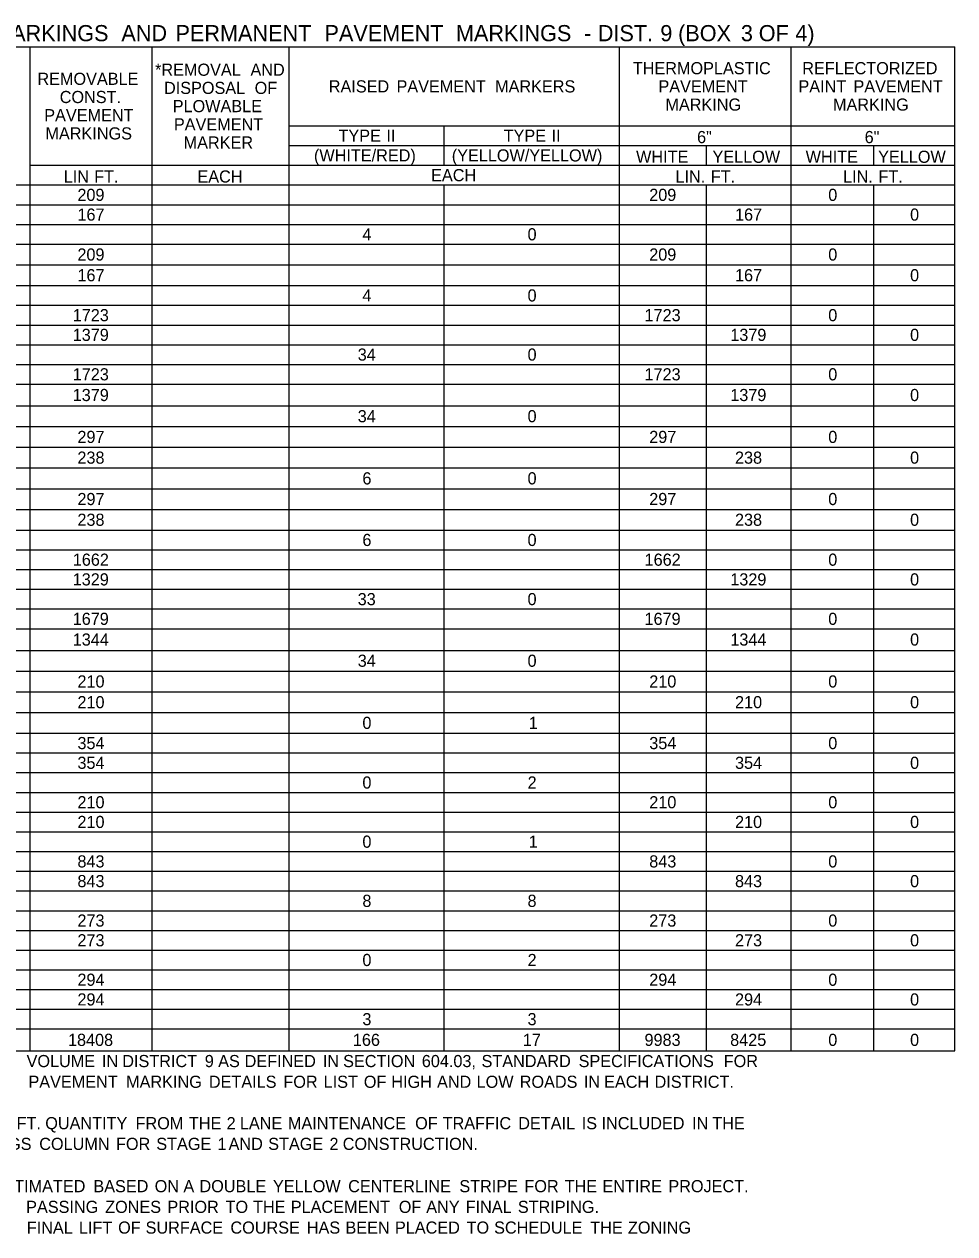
# Model space of a CAD drawing. Extents: x 544420 to 1930787, y -1947044 to 596640.
# Drawn here: x 550212 to 550672, y -1946838 to -1946240 of the extents above; entities that cross this region are included whole.
import ezdxf

# ---------------------------------------------------------------- set-up
doc = ezdxf.new("R2010")
doc.units = 0
doc.layers.add('Default', color=7, linetype='Continuous')

msp = doc.modelspace()

# ---------------------------------------------------------------- linework, layer by layer
at = {"layer": 'Default'}
for p, q in [((549970.43, -1946251.27), (550672.43, -1946251.27)), ((549970.43, -1946251.27), (550275.6, -1946251.27)), ((550215.15, -1946747.55), (550215.15, -1946251.27)), ((550275.6, -1946747.55), (550275.6, -1946251.27)), ((550343.36, -1946747.55), (550343.36, -1946251.27)), ((550506.68, -1946747.55), (550506.68, -1946251.27)), ((550591.5, -1946319.52), (550591.5, -1946251.27)), ((550591.5, -1946747.55), (550591.5, -1946251.27)), ((550672.43, -1946747.55), (550672.43, -1946251.27)), ((550343.36, -1946290.27), (550672.43, -1946290.27)), ((550419.9, -1946309.77), (550419.9, -1946290.27)), ((550343.36, -1946300.02), (550672.43, -1946300.02)), ((550549.58, -1946309.77), (550549.58, -1946300.02)), ((550632.45, -1946309.77), (550632.45, -1946300.02)), ((550215.15, -1946309.77), (550672.43, -1946309.77)), ((550215.15, -1946319.52), (550215.15, -1946309.77)), ((550275.6, -1946319.52), (550275.6, -1946309.77)), ((550343.36, -1946319.52), (550343.36, -1946309.77)), ((550115.7, -1946319.52), (550672.43, -1946319.52)), ((550419.9, -1946747.55), (550419.9, -1946319.52)), ((550506.68, -1946319.52), (550591.5, -1946319.52)), ((550549.58, -1946747.55), (550549.58, -1946319.52)), ((550591.5, -1946319.52), (550672.43, -1946319.52)), ((550632.45, -1946747.55), (550632.45, -1946319.52)), ((550155.19, -1946329.27), (550672.43, -1946329.27)), ((550155.19, -1946339.02), (550672.43, -1946339.02)), ((549970.43, -1946348.77), (550672.43, -1946348.77)), ((550155.19, -1946359.01), (550672.43, -1946359.01)), ((550155.19, -1946369.25), (550672.43, -1946369.25)), ((549970.43, -1946379), (550672.43, -1946379)), ((550155.19, -1946388.75), (550672.43, -1946388.75)), ((550155.19, -1946398.5), (550672.43, -1946398.5)), ((549970.43, -1946408.25), (550672.43, -1946408.25)), ((550155.19, -1946418), (550672.43, -1946418)), ((550155.19, -1946428.72), (550672.43, -1946428.72)), ((549970.43, -1946438.96), (550672.43, -1946438.96)), ((550155.19, -1946449.2), (550672.43, -1946449.2)), ((550155.19, -1946459.44), (550672.43, -1946459.44)), ((549970.43, -1946469.67), (550672.43, -1946469.67)), ((550155.19, -1946479.91), (550672.43, -1946479.91)), ((550155.19, -1946490.15), (550672.43, -1946490.15)), ((549970.43, -1946499.9), (550672.43, -1946499.9)), ((550155.19, -1946509.65), (550672.43, -1946509.65)), ((550155.19, -1946519.4), (550672.43, -1946519.4)), ((549970.43, -1946529.15), (550672.43, -1946529.15)), ((550155.19, -1946538.9), (550672.43, -1946538.9)), ((550155.19, -1946549.62), (550672.43, -1946549.62)), ((549970.43, -1946559.86), (550672.43, -1946559.86)), ((550155.19, -1946570.1), (550672.43, -1946570.1)), ((550155.19, -1946580.34), (550672.43, -1946580.34)), ((549970.43, -1946590.57), (550672.43, -1946590.57)), ((550155.19, -1946600.32), (550672.43, -1946600.32)), ((550155.19, -1946610.07), (550672.43, -1946610.07)), ((549970.43, -1946619.82), (550672.43, -1946619.82)), ((550155.19, -1946629.57), (550672.43, -1946629.57)), ((550155.19, -1946639.32), (550672.43, -1946639.32)), ((549970.43, -1946649.07), (550672.43, -1946649.07)), ((550155.19, -1946658.82), (550672.43, -1946658.82)), ((550155.19, -1946668.57), (550672.43, -1946668.57)), ((549970.43, -1946678.32), (550672.43, -1946678.32)), ((550155.19, -1946688.07), (550672.43, -1946688.07)), ((550155.19, -1946697.82), (550672.43, -1946697.82)), ((549970.43, -1946707.57), (550672.43, -1946707.57)), ((550155.19, -1946717.32), (550672.43, -1946717.32)), ((550155.19, -1946727.07), (550672.43, -1946727.07)), ((549970.43, -1946736.82), (550672.43, -1946736.82)), ((550215.15, -1946747.55), (550215.15, -1946736.82)), ((550275.6, -1946747.55), (550275.6, -1946736.82)), ((550343.36, -1946747.55), (550343.36, -1946736.82)), ((550419.9, -1946747.55), (550419.9, -1946736.82)), ((550506.68, -1946747.55), (550506.68, -1946736.82)), ((550549.58, -1946747.55), (550549.58, -1946736.82)), ((550591.5, -1946747.55), (550591.5, -1946736.82)), ((550632.45, -1946747.55), (550632.45, -1946736.82)), ((549970.43, -1946747.55), (550672.43, -1946747.55))]:
    msp.add_line(p, q, dxfattribs=at)

# ---------------------------------------------------------------- texts
for s, height, p in [(' MARKINGS', 8, (550193.92, -1946248.45)), (' AND', 8, (550257.34, -1946248.45)), (' PERMANENT', 8, (550284.11, -1946248.45)), (' PAVEMENT', 8, (550357.78, -1946248.45)), (' MARKINGS', 8, (550422.77, -1946248.45)), (' -', 8, (550486.18, -1946248.45)), (' DIST.', 8, (550492.93, -1946248.45)), (' 9', 8, (550523.83, -1946248.45)), (' (BOX', 8, (550532.63, -1946248.45)), (' 3', 8, (550563.67, -1946248.45)), (' OF', 8, (550572.5, -1946248.45)), (' 4)', 8, (550590.61, -1946248.45)), ('*REMOVAL', 6, (550276.98, -1946265.52)), (' AND', 6, (550321.91, -1946265.52)), ('THERMOPLASTIC', 6, (550513.2, -1946264.77)), ('REFLECTORIZED', 6, (550597, -1946264.77)), ('REMOVABLE', 6, (550218.8, -1946270.02)), ('DISPOSAL', 6, (550281.39, -1946274.52)), (' OF', 6, (550323.99, -1946274.52)), ('RAISED', 6, (550362.87, -1946273.77)), (' PAVEMENT', 6, (550394.13, -1946273.77)), (' MARKERS', 6, (550442.87, -1946273.77)), ('PAVEMENT', 6, (550525.88, -1946273.77)), ('PAINT', 6, (550595.1, -1946273.77)), (' PAVEMENT', 6, (550620.08, -1946273.77)), ('CONST.', 6, (550229.83, -1946279.02)), ('PLOWABLE', 6, (550285.7, -1946283.52)), ('MARKING', 6, (550529.32, -1946282.77)), ('MARKING', 6, (550612.19, -1946282.77)), ('PAVEMENT', 6, (550222.17, -1946288.02)), ('PAVEMENT', 6, (550286.28, -1946292.52)), ('MARKINGS', 6, (550222.76, -1946297.02)), ('TYPE', 6, (550367.67, -1946298.15)), (' II', 6, (550389.15, -1946298.15)), ('TYPE', 6, (550449.33, -1946298.15)), (' II', 6, (550470.81, -1946298.15)), ('6"', 6, (550544.98, -1946298.82)), ('6"', 6, (550627.85, -1946298.82)), ('MARKER', 6, (550291.1, -1946301.52)), ('(WHITE/RED)', 6, (550355.54, -1946307.9)), ('(YELLOW/YELLOW)', 6, (550423.69, -1946307.9)), ('WHITE', 6, (550514.83, -1946308.57)), ('YELLOW', 6, (550552.61, -1946308.57)), ('WHITE', 6, (550598.68, -1946308.57)), ('YELLOW', 6, (550634.51, -1946308.57)), ('EACH', 6, (550413.46, -1946317.65)), ('LIN', 6, (550231.8, -1946318.32)), (' FT.', 6, (550244.63, -1946318.32)), ('EACH', 6, (550297.93, -1946318.32)), ('LIN.', 6, (550534.3, -1946318.32)), (' FT.', 6, (550549.55, -1946318.32)), ('LIN.', 6, (550617.17, -1946318.32)), (' FT.', 6, (550632.43, -1946318.32)), ('209', 6, (550238.57, -1946327.4)), ('209', 6, (550521.32, -1946327.4)), ('0', 6, (550609.85, -1946327.4)), ('167', 6, (550238.58, -1946337.15)), ('167', 6, (550563.74, -1946337.15)), ('0', 6, (550650.31, -1946337.15)), ('4', 6, (550379.51, -1946346.9)), ('0', 6, (550461.16, -1946346.9)), ('209', 6, (550238.57, -1946356.89)), ('209', 6, (550521.32, -1946356.89)), ('0', 6, (550609.85, -1946356.89)), ('167', 6, (550238.58, -1946367.13)), ('167', 6, (550563.74, -1946367.13)), ('0', 6, (550650.31, -1946367.13)), ('4', 6, (550379.51, -1946377.12)), ('0', 6, (550461.16, -1946377.12)), ('1723', 6, (550236.25, -1946386.87)), ('1723', 6, (550519, -1946386.87)), ('0', 6, (550609.85, -1946386.87)), ('1379', 6, (550236.24, -1946396.62)), ('1379', 6, (550561.4, -1946396.62)), ('0', 6, (550650.31, -1946396.62)), ('34', 6, (550377.18, -1946406.37)), ('0', 6, (550461.16, -1946406.37)), ('1723', 6, (550236.25, -1946416.12)), ('1723', 6, (550519, -1946416.12)), ('0', 6, (550609.85, -1946416.12)), ('1379', 6, (550236.24, -1946426.36)), ('1379', 6, (550561.4, -1946426.36)), ('0', 6, (550650.31, -1946426.36)), ('34', 6, (550377.18, -1946436.84)), ('0', 6, (550461.16, -1946436.84)), ('297', 6, (550238.58, -1946447.08)), ('297', 6, (550521.33, -1946447.08)), ('0', 6, (550609.85, -1946447.08)), ('238', 6, (550238.57, -1946457.32)), ('238', 6, (550563.73, -1946457.32)), ('0', 6, (550650.31, -1946457.32)), ('6', 6, (550379.49, -1946467.56)), ('0', 6, (550461.16, -1946467.56)), ('297', 6, (550238.58, -1946477.79)), ('297', 6, (550521.33, -1946477.79)), ('0', 6, (550609.85, -1946477.79)), ('238', 6, (550238.57, -1946488.03)), ('238', 6, (550563.73, -1946488.03)), ('0', 6, (550650.31, -1946488.03)), ('6', 6, (550379.49, -1946498.02)), ('0', 6, (550461.16, -1946498.02)), ('1662', 6, (550236.28, -1946507.77)), ('1662', 6, (550519.03, -1946507.77)), ('0', 6, (550609.85, -1946507.77)), ('1329', 6, (550236.24, -1946517.52)), ('1329', 6, (550561.4, -1946517.52)), ('0', 6, (550650.31, -1946517.52)), ('33', 6, (550377.16, -1946527.27)), ('0', 6, (550461.16, -1946527.27)), ('1679', 6, (550236.24, -1946537.02)), ('1679', 6, (550518.99, -1946537.02)), ('0', 6, (550609.85, -1946537.02)), ('1344', 6, (550236.26, -1946547.26)), ('1344', 6, (550561.42, -1946547.26)), ('0', 6, (550650.31, -1946547.26)), ('34', 6, (550377.18, -1946557.74)), ('0', 6, (550461.16, -1946557.74)), ('210', 6, (550238.59, -1946567.98)), ('210', 6, (550521.34, -1946567.98)), ('0', 6, (550609.85, -1946567.98)), ('210', 6, (550238.59, -1946578.22)), ('210', 6, (550563.75, -1946578.22)), ('0', 6, (550650.31, -1946578.22)), ('0', 6, (550379.5, -1946588.46)), ('1', 6, (550461.73, -1946588.46)), ('354', 6, (550238.59, -1946598.45)), ('354', 6, (550521.34, -1946598.45)), ('0', 6, (550609.85, -1946598.45)), ('354', 6, (550238.59, -1946608.2)), ('354', 6, (550563.75, -1946608.2)), ('0', 6, (550650.31, -1946608.2)), ('0', 6, (550379.5, -1946617.95)), ('2', 6, (550461.18, -1946617.95)), ('210', 6, (550238.59, -1946627.7)), ('210', 6, (550521.34, -1946627.7)), ('0', 6, (550609.85, -1946627.7)), ('210', 6, (550238.59, -1946637.45)), ('210', 6, (550563.75, -1946637.45)), ('0', 6, (550650.31, -1946637.45)), ('0', 6, (550379.5, -1946647.2)), ('1', 6, (550461.73, -1946647.2)), ('843', 6, (550238.58, -1946656.95)), ('843', 6, (550521.33, -1946656.95)), ('0', 6, (550609.85, -1946656.95)), ('843', 6, (550238.58, -1946666.7)), ('843', 6, (550563.74, -1946666.7)), ('0', 6, (550650.31, -1946666.7)), ('8', 6, (550379.49, -1946676.45)), ('8', 6, (550461.14, -1946676.45)), ('273', 6, (550238.58, -1946686.2)), ('273', 6, (550521.33, -1946686.2)), ('0', 6, (550609.85, -1946686.2)), ('273', 6, (550238.58, -1946695.95)), ('273', 6, (550563.74, -1946695.95)), ('0', 6, (550650.31, -1946695.95)), ('0', 6, (550379.5, -1946705.7)), ('2', 6, (550461.18, -1946705.7)), ('294', 6, (550238.59, -1946715.45)), ('294', 6, (550521.34, -1946715.45)), ('0', 6, (550609.85, -1946715.45)), ('294', 6, (550238.59, -1946725.2)), ('294', 6, (550563.75, -1946725.2)), ('0', 6, (550650.31, -1946725.2)), ('3', 6, (550379.49, -1946734.95)), ('3', 6, (550461.15, -1946734.95)), ('18408', 6, (550233.91, -1946745.19)), ('166', 6, (550374.79, -1946745.19)), ('17', 6, (550458.81, -1946745.19)), ('9983', 6, (550518.99, -1946745.19)), ('8425', 6, (550561.34, -1946745.19)), ('0', 6, (550609.85, -1946745.19)), ('0', 6, (550650.31, -1946745.19)), (' VOLUME', 6, (550211.21, -1946755.67)), (' IN', 6, (550248.49, -1946755.67)), (' DISTRICT', 6, (550258.52, -1946755.67)), (' 9', 6, (550299.33, -1946755.67)), (' AS', 6, (550305.95, -1946755.67)), (' DEFINED', 6, (550319.03, -1946755.67)), (' IN', 6, (550357.71, -1946755.67)), (' SECTION', 6, (550367.73, -1946755.67)), (' 604.03,', 6, (550406.64, -1946755.67)), (' STANDARD', 6, (550436.18, -1946755.67)), (' SPECIFICATIONS', 6, (550484.18, -1946755.67)), (' FOR', 6, (550555.94, -1946755.67)), (' PAVEMENT', 6, (550212.14, -1946765.91)), (' MARKING', 6, (550260.42, -1946765.91)), (' DETAILS', 6, (550301.35, -1946765.91)), (' FOR', 6, (550338.19, -1946765.91)), (' LIST', 6, (550358.1, -1946765.91)), (' OF', 6, (550377.96, -1946765.91)), (' HIGH', 6, (550391.55, -1946765.91)), (' AND', 6, (550414.16, -1946765.91)), (' LOW', 6, (550433.74, -1946765.91)), (' ROADS', 6, (550455.06, -1946765.91)), (' IN', 6, (550486.77, -1946765.91)), (' EACH', 6, (550496.79, -1946765.91)), (' DISTRICT.', 6, (550521.74, -1946765.91)), (' FT.', 6, (550206.28, -1946786.38)), (' QUANTITY', 6, (550220.45, -1946786.38)), (' FROM', 6, (550265.1, -1946786.38)), (' THE', 6, (550291.48, -1946786.38)), (' 2', 6, (550310.13, -1946786.38)), (' LANE', 6, (550316.67, -1946786.38)), (' MAINTENANCE', 6, (550340.45, -1946786.38)), (' OF', 6, (550403.35, -1946786.38)), (' TRAFFIC', 6, (550416.94, -1946786.38)), (' DETAIL', 6, (550454.33, -1946786.38)), (' IS', 6, (550485.71, -1946786.38)), (' INCLUDED', 6, (550495.52, -1946786.38)), (' IN', 6, (550540.26, -1946786.38)), (' THE', 6, (550550.28, -1946786.38)), (' MARKINGS', 6, (550170.86, -1946796.62)), (' COLUMN', 6, (550217.47, -1946796.62)), (' FOR', 6, (550255.44, -1946796.62)), (' STAGE', 6, (550275.35, -1946796.62)), (' 1', 6, (550305.65, -1946796.62)), (' AND', 6, (550311.1, -1946796.62)), (' STAGE', 6, (550330.68, -1946796.62)), (' 2', 6, (550360.98, -1946796.62)), (' CONSTRUCTION.', 6, (550367.53, -1946796.62)), (' ESTIMATED', 6, (550194.38, -1946817.52)), (' BASED', 6, (550244.24, -1946817.52)), (' ON', 6, (550274.55, -1946817.52)), (' A', 6, (550288.76, -1946817.52)), (' DOUBLE', 6, (550296.7, -1946817.52)), (' YELLOW', 6, (550333.06, -1946817.52)), (' CENTERLINE', 6, (550370.23, -1946817.52)), (' STRIPE', 6, (550425.21, -1946817.52)), (' FOR', 6, (550457.38, -1946817.52)), (' THE', 6, (550477.29, -1946817.52)), (' ENTIRE', 6, (550495.94, -1946817.52)), (' PROJECT.', 6, (550528.56, -1946817.52)), (' PASSING', 6, (550210.99, -1946827.76)), (' ZONES', 6, (550250.06, -1946827.76)), (' PRIOR', 6, (550280.84, -1946827.76)), (' TO', 6, (550309.6, -1946827.76)), (' THE', 6, (550323.2, -1946827.76)), (' PLACEMENT', 6, (550341.85, -1946827.76)), (' OF', 6, (550395.25, -1946827.76)), (' ANY', 6, (550408.84, -1946827.76)), (' FINAL', 6, (550428.34, -1946827.76)), (' STRIPING.', 6, (550454.13, -1946827.76)), (' FINAL', 6, (550211.3, -1946838)), (' LIFT', 6, (550237.09, -1946838)), (' OF', 6, (550256.48, -1946838)), (' SURFACE', 6, (550270.06, -1946838)), (' COURSE', 6, (550312.01, -1946838)), (' HAS', 6, (550349.76, -1946838)), (' BEEN', 6, (550368.89, -1946838)), (' PLACED', 6, (550393.36, -1946838)), (' TO', 6, (550428.79, -1946838)), (' SCHEDULE', 6, (550442.39, -1946838)), (' THE', 6, (550489.93, -1946838)), (' ZONING', 6, (550508.58, -1946838))]:
    msp.add_text(s, height=height, dxfattribs=at).set_placement(p)

doc.saveas('drawing.dxf')
